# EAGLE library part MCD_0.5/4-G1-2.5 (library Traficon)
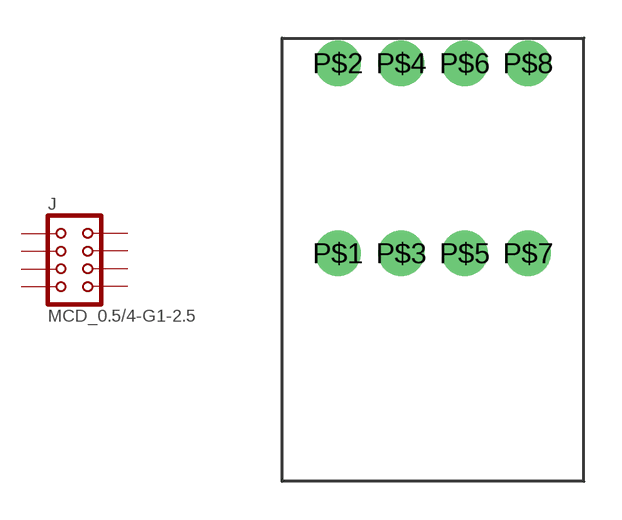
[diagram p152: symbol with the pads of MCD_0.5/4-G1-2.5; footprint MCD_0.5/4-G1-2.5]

Designator prefix J

## MCD_0.5/4-G1-2.5  [MCD_0.5/4-G1-2.5]
P$1  P$1  pas
P$2  P$2  pas
P$3  P$3  pas
P$4  P$4  pas
P$5  P$5  pas
P$6  P$6  pas
P$7  P$7  pas
P$8  P$8  pas

## Footprint MCD_0.5/4-G1-2.5 (pad centres in mm)
drill 1.2 round: P$1 -2.88,1.38; P$2 -2.88,8.88; P$3 -0.38,1.38; P$4 -0.38,8.88; P$5 2.12,1.38; P$6 2.12,8.88; P$7 4.62,1.38; P$8 4.62,8.88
